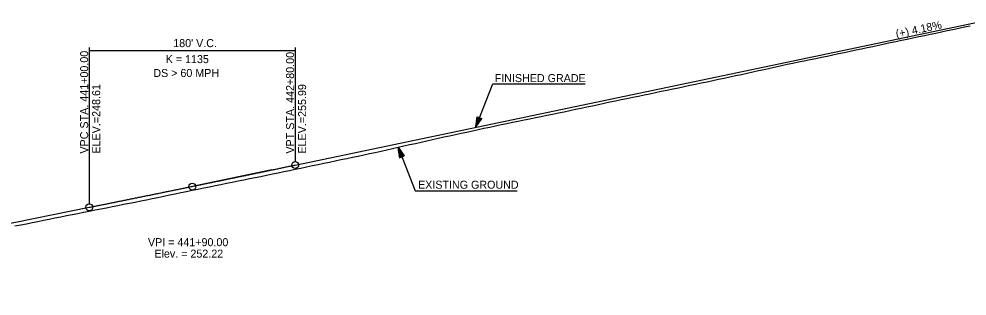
# Model space of a CAD drawing. Extents: x 69 to 2003113, y 512 to 837401.
# Drawn here: x 1922402 to 1923230, y 828628 to 828870 of the extents above; entities that cross this region are included whole.
import ezdxf

# ---------------------------------------------------------------- set-up
doc = ezdxf.new("R2010")
doc.units = 0
for name, color, linetype in [('BR_CENTER LINE BASELINE', 7, 'Continuous'), ('BR_CONCRETE', 7, 'Continuous'), ('BR_GRID DOTS', 7, 'Continuous'), ('BR_GRID LINES', 7, 'Continuous'), ('BR_TEXT', 7, 'Continuous'), ('RD_PD_ALT1_TrvlWay', 7, 'Continuous'), ('RD_SHT_IplotShp', 7, 'Continuous')]:
    doc.layers.add(name, color=color, linetype=linetype)

msp = doc.modelspace()

# ---------------------------------------------------------------- linework, layer by layer
at = {"layer": 'BR_CENTER LINE BASELINE'}
for p, q in [((1922622.64, 828738.45), (1922556.08, 828724.54)), ((1922483.53, 828709.93), (1922550.2, 828723.33))]:
    msp.add_line(p, q, dxfattribs=at)
msp.add_circle((1922553.14, 828723.92), 3, dxfattribs=at)
at = {"layer": 'BR_GRID DOTS'}
for p, q in [((1922463.14, 828845.23), (1922463.14, 828708.83)), ((1922643.14, 828845.23), (1922643.14, 828745.73)), ((1922463.14, 828842.73), (1922643.14, 828842.73))]:
    msp.add_line(p, q, dxfattribs=at)
for centre in [(1922643.14, 828742.73), (1922463.14, 828705.83)]:
    msp.add_circle(centre, 3, dxfattribs=at)
at = {"layer": 'BR_GRID LINES'}
for p, q in [((1922643.14, 828742.73), (1923253.14, 828870.2)), ((1922078.14, 828628.43), (1922463.14, 828705.83))]:
    msp.add_line(p, q, dxfattribs=at)
msp.add_spline([(1922463.14, 828705.83), (1922466.74, 828706.55), (1922470.34, 828707.28), (1922473.94, 828708), (1922477.54, 828708.73), (1922481.14, 828709.46), (1922484.74, 828710.18), (1922488.34, 828710.91), (1922491.94, 828711.64), (1922495.54, 828712.37), (1922499.14, 828713.1), (1922502.74, 828713.83), (1922506.34, 828714.56), (1922509.94, 828715.29), (1922513.54, 828716.02), (1922517.14, 828716.75), (1922520.74, 828717.48), (1922524.34, 828718.22), (1922527.94, 828718.95), (1922531.54, 828719.68), (1922535.14, 828720.42), (1922538.74, 828721.15), (1922542.34, 828721.89), (1922545.94, 828722.63), (1922549.54, 828723.36), (1922553.14, 828724.1), (1922556.74, 828724.84), (1922560.34, 828725.58), (1922563.94, 828726.32), (1922567.54, 828727.06), (1922571.14, 828727.8), (1922574.74, 828728.54), (1922578.34, 828729.28), (1922581.94, 828730.02), (1922585.54, 828730.77), (1922589.14, 828731.51), (1922592.74, 828732.25), (1922596.34, 828733), (1922599.94, 828733.74), (1922603.54, 828734.49), (1922607.14, 828735.24), (1922610.74, 828735.98), (1922614.34, 828736.73), (1922617.94, 828737.48), (1922621.54, 828738.23), (1922625.14, 828738.98), (1922628.74, 828739.73), (1922632.34, 828740.48), (1922635.94, 828741.23), (1922639.54, 828741.98), (1922643.14, 828742.73)], degree=3, dxfattribs=at)
at = {"layer": 'BR_TEXT'}
for points in [[(1922863.14, 828786.25), (1922868.14, 828787.27), (1922873.14, 828788.29), (1922878.14, 828789.31), (1922883.14, 828790.33), (1922888.14, 828791.4), (1922893.14, 828792.43), (1922898.14, 828793.45), (1922903.14, 828794.52), (1922908.14, 828795.59), (1922913.14, 828796.67), (1922918.14, 828797.76), (1922923.14, 828798.8), (1922928.14, 828799.82), (1922933.14, 828800.83), (1922938.14, 828801.85), (1922943.14, 828802.91), (1922948.14, 828803.95), (1922953.14, 828804.96), (1922958.14, 828806.05), (1922963.14, 828807.11), (1922968.14, 828808.15), (1922973.14, 828809.19), (1922978.14, 828810.23), (1922983.14, 828811.24), (1922988.14, 828812.3), (1922993.14, 828813.35), (1922998.14, 828814.41), (1923003.14, 828815.48), (1923008.14, 828816.52), (1923013.14, 828817.56), (1923018.14, 828818.6), (1923023.14, 828819.65), (1923028.14, 828820.75), (1923033.14, 828821.84), (1923038.14, 828822.91), (1923043.14, 828824.04), (1923048.14, 828825.13), (1923053.14, 828826.22), (1923058.14, 828827.33), (1923063.14, 828828.44), (1923068.14, 828829.55), (1923073.14, 828830.66), (1923078.14, 828831.77), (1923083.14, 828832.71), (1923088.14, 828833.69), (1923093.14, 828834.77), (1923098.14, 828835.79), (1923103.14, 828836.82), (1923108.14, 828837.88), (1923113.14, 828838.97), (1923118.14, 828840.08), (1923123.14, 828841.04), (1923128.14, 828842.07), (1923133.14, 828843.19), (1923138.14, 828844.2), (1923143.14, 828845.24), (1923148.14, 828846.3), (1923153.14, 828847.39), (1923158.14, 828848.48), (1923163.14, 828849.55), (1923168.14, 828850.54), (1923173.14, 828851.58), (1923178.14, 828852.66), (1923183.14, 828853.75), (1923188.14, 828854.82), (1923193.14, 828855.87), (1923198.14, 828856.91), (1923203.14, 828857.96), (1923208.14, 828858.98), (1923213.14, 828860.04), (1923218.14, 828861.09), (1923223.14, 828862.13), (1923228.14, 828863.21), (1923233.14, 828864.21)], [(1922398.14, 828689.56), (1922403.14, 828690.55), (1922408.14, 828691.54), (1922413.14, 828692.54), (1922418.14, 828693.58), (1922423.14, 828694.58), (1922428.14, 828695.57), (1922433.14, 828696.56), (1922438.14, 828697.55), (1922443.14, 828698.55), (1922448.14, 828699.54), (1922453.14, 828700.53), (1922458.14, 828701.52), (1922463.14, 828702.53), (1922468.14, 828703.55), (1922473.14, 828704.54), (1922478.14, 828705.52), (1922483.14, 828706.51), (1922488.14, 828707.53), (1922493.14, 828708.51), (1922498.14, 828709.48), (1922503.14, 828710.43), (1922508.14, 828711.44), (1922513.14, 828712.43), (1922518.14, 828713.46), (1922523.14, 828714.49), (1922528.14, 828715.52), (1922533.14, 828716.59), (1922538.14, 828717.64), (1922543.14, 828718.68), (1922548.14, 828719.72), (1922553.14, 828720.76), (1922558.14, 828721.79), (1922563.14, 828722.8), (1922568.14, 828723.8), (1922573.14, 828724.8), (1922578.14, 828725.79), (1922583.14, 828726.8), (1922588.14, 828727.82), (1922593.14, 828728.85), (1922598.14, 828729.88), (1922603.14, 828730.89), (1922608.14, 828731.88), (1922613.14, 828732.87), (1922618.14, 828733.88), (1922623.14, 828734.94), (1922628.14, 828736), (1922633.14, 828737.05), (1922638.14, 828738.1), (1922643.14, 828739.1), (1922648.14, 828740.12), (1922653.14, 828741.15), (1922658.14, 828742.19), (1922663.14, 828743.23), (1922668.14, 828744.26), (1922673.14, 828745.31), (1922678.14, 828746.37), (1922683.14, 828747.43), (1922688.14, 828748.48), (1922693.14, 828749.52), (1922698.14, 828750.6), (1922703.14, 828751.65), (1922708.14, 828752.71), (1922713.14, 828753.79), (1922718.14, 828754.92), (1922723.14, 828756.06), (1922728.14, 828757.19), (1922733.14, 828758.3), (1922738.14, 828759.41), (1922743.14, 828760.52), (1922748.14, 828761.63), (1922753.14, 828762.74), (1922758.14, 828763.87), (1922763.14, 828765), (1922768.14, 828766.12), (1922773.14, 828767.21), (1922778.14, 828768.29), (1922783.14, 828769.37), (1922788.14, 828770.45), (1922793.14, 828771.54), (1922798.14, 828772.71), (1922803.14, 828773.79), (1922808.14, 828774.83), (1922813.14, 828775.92), (1922818.14, 828776.99), (1922823.14, 828778.04), (1922828.14, 828779.09), (1922833.14, 828780.11), (1922838.14, 828781.14), (1922843.14, 828782.16), (1922848.14, 828783.16), (1922853.14, 828784.17), (1922858.14, 828785.21), (1922863.14, 828786.25)]]:
    msp.add_lwpolyline(points, dxfattribs=at)
at = {"layer": 'RD_PD_ALT1_TrvlWay'}
for p, q in [((1922800.9, 828775.7), (1922815.86, 828813.65)), ((1922815.86, 828813.65), (1922896.65, 828813.65)), ((1922800.9, 828775.7), (1922802.11, 828784.9)), ((1922800.9, 828775.7), (1922802.11, 828784.9)), ((1922804.2, 828784.07), (1922800.9, 828775.7)), ((1922804.2, 828784.07), (1922800.9, 828775.7)), ((1922800.9, 828775.7), (1922806.3, 828783.25)), ((1922800.9, 828775.7), (1922806.3, 828783.25)), ((1922802.11, 828784.9), (1922806.3, 828783.25)), ((1922802.11, 828784.9), (1922806.3, 828783.25)), ((1922733.08, 828758.3), (1922748.04, 828720.34)), ((1922736.38, 828749.93), (1922733.08, 828758.3)), ((1922733.08, 828758.3), (1922738.48, 828750.75)), ((1922733.08, 828758.3), (1922734.29, 828749.1)), ((1922734.29, 828749.1), (1922738.48, 828750.75)), ((1922748.04, 828720.34), (1922837.23, 828720.34))]:
    msp.add_line(p, q, dxfattribs=at)
for points in [[(1922804.1, 828783.99), (1922801.03, 828776.2), (1922804.07, 828784.06), (1922801.1, 828776.59), (1922803.97, 828784.06), (1922801.13, 828776.86), (1922803.86, 828784.09), (1922801.16, 828777.19), (1922803.78, 828784.14), (1922801.23, 828777.68), (1922803.66, 828784.2), (1922801.32, 828778.2), (1922803.55, 828784.21), (1922801.38, 828778.6), (1922803.47, 828784.26), (1922801.44, 828779.06), (1922803.36, 828784.24), (1922801.49, 828779.46), (1922803.3, 828784.35), (1922801.53, 828779.8), (1922803.17, 828784.36), (1922801.59, 828780.3), (1922803.07, 828784.42), (1922801.7, 828780.9), (1922802.97, 828784.48), (1922801.7, 828781.31), (1922802.87, 828784.52), (1922801.79, 828781.94), (1922802.75, 828784.52), (1922801.89, 828782.44), (1922802.65, 828784.62), (1922801.94, 828782.88), (1922802.55, 828784.62), (1922801.98, 828783.29), (1922802.47, 828784.72), (1922802.06, 828783.78), (1922802.35, 828784.68), (1922802.13, 828784.33), (1922802.23, 828784.69)], [(1922804.1, 828783.99), (1922801.03, 828776.2), (1922804.07, 828784.06), (1922801.1, 828776.59), (1922803.97, 828784.06), (1922801.13, 828776.86), (1922803.86, 828784.09), (1922801.16, 828777.19), (1922803.78, 828784.14), (1922801.23, 828777.68), (1922803.66, 828784.2), (1922801.32, 828778.2), (1922803.55, 828784.21), (1922801.38, 828778.6), (1922803.47, 828784.26), (1922801.44, 828779.06), (1922803.36, 828784.24), (1922801.49, 828779.46), (1922803.3, 828784.35), (1922801.53, 828779.8), (1922803.17, 828784.36), (1922801.59, 828780.3), (1922803.07, 828784.42), (1922801.7, 828780.9), (1922802.97, 828784.48), (1922801.7, 828781.31), (1922802.87, 828784.52), (1922801.79, 828781.94), (1922802.75, 828784.52), (1922801.89, 828782.44), (1922802.65, 828784.62), (1922801.94, 828782.88), (1922802.55, 828784.62), (1922801.98, 828783.29), (1922802.47, 828784.72), (1922802.06, 828783.78), (1922802.35, 828784.68), (1922802.13, 828784.33), (1922802.23, 828784.69)], [(1922801.18, 828776.22), (1922804.22, 828783.94), (1922801.34, 828776.47), (1922804.33, 828783.9), (1922801.49, 828776.71), (1922804.41, 828783.91), (1922801.68, 828776.92), (1922804.47, 828783.87), (1922801.88, 828777.18), (1922804.57, 828783.85), (1922802.06, 828777.43), (1922804.63, 828783.82), (1922802.27, 828777.73), (1922804.73, 828783.8), (1922802.52, 828778.09), (1922804.84, 828783.74), (1922802.72, 828778.41), (1922804.93, 828783.75), (1922802.95, 828778.74), (1922805.01, 828783.7), (1922803.19, 828779.05), (1922805.09, 828783.66), (1922803.43, 828779.39), (1922805.14, 828783.58), (1922803.75, 828779.85), (1922805.24, 828783.58), (1922803.98, 828780.14), (1922805.32, 828783.59), (1922804.27, 828780.52), (1922805.4, 828783.52), (1922804.51, 828780.93), (1922805.49, 828783.46), (1922804.74, 828781.24), (1922805.58, 828783.37), (1922804.99, 828781.52), (1922805.65, 828783.34), (1922805.27, 828781.99), (1922805.8, 828783.36), (1922805.46, 828782.26), (1922805.93, 828783.31), (1922805.64, 828782.42), (1922806.04, 828783.17), (1922806.16, 828783.22), (1922806, 828783.18)], [(1922801.18, 828776.22), (1922804.22, 828783.94), (1922801.34, 828776.47), (1922804.33, 828783.9), (1922801.49, 828776.71), (1922804.41, 828783.91), (1922801.68, 828776.92), (1922804.47, 828783.87), (1922801.88, 828777.18), (1922804.57, 828783.85), (1922802.06, 828777.43), (1922804.63, 828783.82), (1922802.27, 828777.73), (1922804.73, 828783.8), (1922802.52, 828778.09), (1922804.84, 828783.74), (1922802.72, 828778.41), (1922804.93, 828783.75), (1922802.95, 828778.74), (1922805.01, 828783.7), (1922803.19, 828779.05), (1922805.09, 828783.66), (1922803.43, 828779.39), (1922805.14, 828783.58), (1922803.75, 828779.85), (1922805.24, 828783.58), (1922803.98, 828780.14), (1922805.32, 828783.59), (1922804.27, 828780.52), (1922805.4, 828783.52), (1922804.51, 828780.93), (1922805.49, 828783.46), (1922804.74, 828781.24), (1922805.58, 828783.37), (1922804.99, 828781.52), (1922805.65, 828783.34), (1922805.27, 828781.99), (1922805.8, 828783.36), (1922805.46, 828782.26), (1922805.93, 828783.31), (1922805.64, 828782.42), (1922806.04, 828783.17), (1922806.16, 828783.22), (1922806, 828783.18)], [(1922736.28, 828750.01), (1922733.21, 828757.8), (1922736.25, 828749.93), (1922733.28, 828757.41), (1922736.15, 828749.93), (1922733.31, 828757.14), (1922736.04, 828749.91), (1922733.34, 828756.81), (1922735.96, 828749.86), (1922733.41, 828756.32), (1922735.84, 828749.79), (1922733.5, 828755.79), (1922735.73, 828749.79), (1922733.55, 828755.4), (1922735.65, 828749.74), (1922733.61, 828754.94), (1922735.54, 828749.75), (1922733.67, 828754.54), (1922735.48, 828749.65), (1922733.71, 828754.2), (1922735.34, 828749.64), (1922733.76, 828753.7), (1922735.25, 828749.58), (1922733.88, 828753.1), (1922735.15, 828749.52), (1922733.88, 828752.68), (1922735.05, 828749.48), (1922733.97, 828752.06), (1922734.93, 828749.47), (1922734.07, 828751.56), (1922734.83, 828749.37), (1922734.12, 828751.12), (1922734.73, 828749.37), (1922734.16, 828750.71), (1922734.64, 828749.28), (1922734.23, 828750.22), (1922734.53, 828749.32), (1922734.31, 828749.67), (1922734.41, 828749.31)], [(1922733.36, 828757.78), (1922736.4, 828750.05), (1922733.52, 828757.52), (1922736.51, 828750.09), (1922733.67, 828757.28), (1922736.59, 828750.09), (1922733.85, 828757.08), (1922736.65, 828750.13), (1922734.06, 828756.82), (1922736.74, 828750.15), (1922734.23, 828756.57), (1922736.81, 828750.18), (1922734.45, 828756.27), (1922736.91, 828750.19), (1922734.69, 828755.91), (1922737.02, 828750.26), (1922734.9, 828755.59), (1922737.1, 828750.25), (1922735.13, 828755.26), (1922737.18, 828750.3), (1922735.37, 828754.95), (1922737.27, 828750.34), (1922735.61, 828754.6), (1922737.32, 828750.42), (1922735.93, 828754.15), (1922737.42, 828750.42), (1922736.16, 828753.86), (1922737.5, 828750.41), (1922736.45, 828753.48), (1922737.58, 828750.48), (1922736.69, 828753.07), (1922737.67, 828750.53), (1922736.92, 828752.76), (1922737.76, 828750.63), (1922737.17, 828752.48), (1922737.83, 828750.66), (1922737.45, 828752.01), (1922737.97, 828750.63), (1922737.64, 828751.74), (1922738.11, 828750.69), (1922737.82, 828751.57), (1922738.22, 828750.83), (1922738.34, 828750.78), (1922738.18, 828750.82)]]:
    msp.add_lwpolyline(points, dxfattribs=at)

# ---------------------------------------------------------------- texts
at = {"layer": 'BR_CENTER LINE BASELINE'}
msp.add_text('(+) 4.18%', height=7, rotation=11.80288, dxfattribs=at).set_placement((1923168.84, 828853.64))
at = {"layer": 'BR_CONCRETE'}
for s, p in [('VPC STA. 441+00.00 ', (1922462.14, 828752.73)), ('VPT STA. 442+80.00 ', (1922642.14, 828752.73)), ('ELEV.=248.61', (1922472.64, 828752.73)), ('ELEV.=255.99', (1922652.64, 828752.73))]:
    msp.add_text(s, height=7, rotation=90, dxfattribs=at).set_placement(p)
at = {"layer": 'BR_GRID DOTS'}
for s, p in [("180' V.C.", (1922536.5, 828845.64)), ('K = 1135', (1922529.92, 828831.69)), ('DS > 60 MPH', (1922519.1, 828819.56))]:
    msp.add_text(s, height=7, dxfattribs=at).set_placement(p)
at = {"layer": 'RD_PD_ALT1_TrvlWay'}
for s, p in [('FINISHED GRADE', (1922817.5, 828815.12)), ('EXISTING GROUND', (1922750.51, 828722.07))]:
    msp.add_text(s, height=7, dxfattribs=at).set_placement(p)
at = {"layer": 'RD_SHT_IplotShp'}
for s, p in [('VPI = 441+90.00', (1922514.4, 828671.92)), ('Elev. = 252.22', (1922520.05, 828661.92))]:
    msp.add_text(s, height=7, dxfattribs=at).set_placement(p)

doc.saveas('drawing.dxf')
